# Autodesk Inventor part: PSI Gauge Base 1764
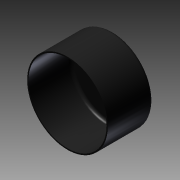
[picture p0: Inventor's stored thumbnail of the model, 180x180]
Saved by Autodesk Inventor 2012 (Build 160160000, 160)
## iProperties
Created: 2010-02
Part Number: PSI Gauge Base 1764
Document SubType Name: Modeling
Designer: jgehrig
Density: 1 g/cm^3
Material: Default
Author: jgehrig
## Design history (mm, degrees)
sketch "Sketch1"
  geometry: C1 r 20.32 at (0, 0); C2 r 19.685 at (0, 0); 1 further point
  constraints: 2 centre point, 2 coincident
  dimensions: "d0" = 40.64 diameter of C1; "d1" = 39.37 diameter of C2
extrude "Extrusion1" new body sketch "Sketch1" distance "d2" = 21.59; taper "d3" = 0 deg
sketch "Sketch2"
  geometry: C1 r 20.32 at (0, 0) reference
extrude "Extrusion2" join sketch "Sketch2" distance "d4" = 1.27; taper "d5" = 0 deg
fillet "Fillet1" dims "d6" = 1.5875
body "Solid1"
